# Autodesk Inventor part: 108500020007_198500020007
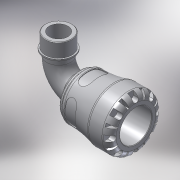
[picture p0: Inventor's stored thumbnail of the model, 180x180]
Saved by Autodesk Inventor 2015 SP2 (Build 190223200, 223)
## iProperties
Created: 2016-12
Part Number: 108500020007_198500020007
Material: PVC-Piping
Description: PLASSON 90° ELBOW WITH THREADED MALE OFFTAKE 20X3/4" SERIES 1
Document SubType Name: Modeling
Designer: KIM
Mass: 68.5548 g
Surface Area: 187.544 cm^2
Volume: 48.9677 cm^3
Density: 1.4 g/cm^3
Appearance: Smooth - White
Author: KIM
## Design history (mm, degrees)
derived "1085.ipt"
feature "Solid1::1085.ipt"
tag "TaggingFeature1"
body "Solid1"
other parameters: "d1" = 18.9, "d3" = 25, "d4" = 41, "d8" = 34.85, "d13" = 6.4, "d14" = 6.4, "d15" = 0, "d17" = 360 deg, "d19" = 8 deg, "d20" = 0.4, "d21" = 0.4, "d22" = 8 deg, "d24" = 0, "d26" = 360 deg, "d33" = 4.1, "d43" = 31.98, "d51" = 0.41, "d54" = 7, "d55" = 4.4, "d57" = 12.544, "d58" = 0, "d74" = 0, "d78" = 45, "d82" = 0.4, "d115" = 360 deg, "d207" = 90 deg, "d228" = 5.95, "d247" = 0.82, "d248" = 2.7, "d268" = 19.1675, "d269" = 2.7, "d270" = 66, "d276" = 26.441, "d277" = 17, "d278" = 29.0851, "d279" = 42, "d280" = 18.7, "d281" = 3.96615, "d283" = 23.7969, "d286" = 0, "d287" = 0, "d288" = 18.5087, "d290" = 4.09155, "d292" = 30 deg, "E_" = 41, "l_" = 45, "A_" = 66, "A_1" = 42, "l_2" = 17, "R_" = 26.441, "d9" = 8, "d11" = 41, "d12" = 25, "d289" = 18.5087
